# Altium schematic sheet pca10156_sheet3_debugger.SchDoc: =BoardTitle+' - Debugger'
size A3; Organization: Nordic Semiconductor; DocumentNumber: 3; SheetNumber: 3; SheetTotal: 8; CompanyName: Nordic Semiconductor; DocumentSize: A4
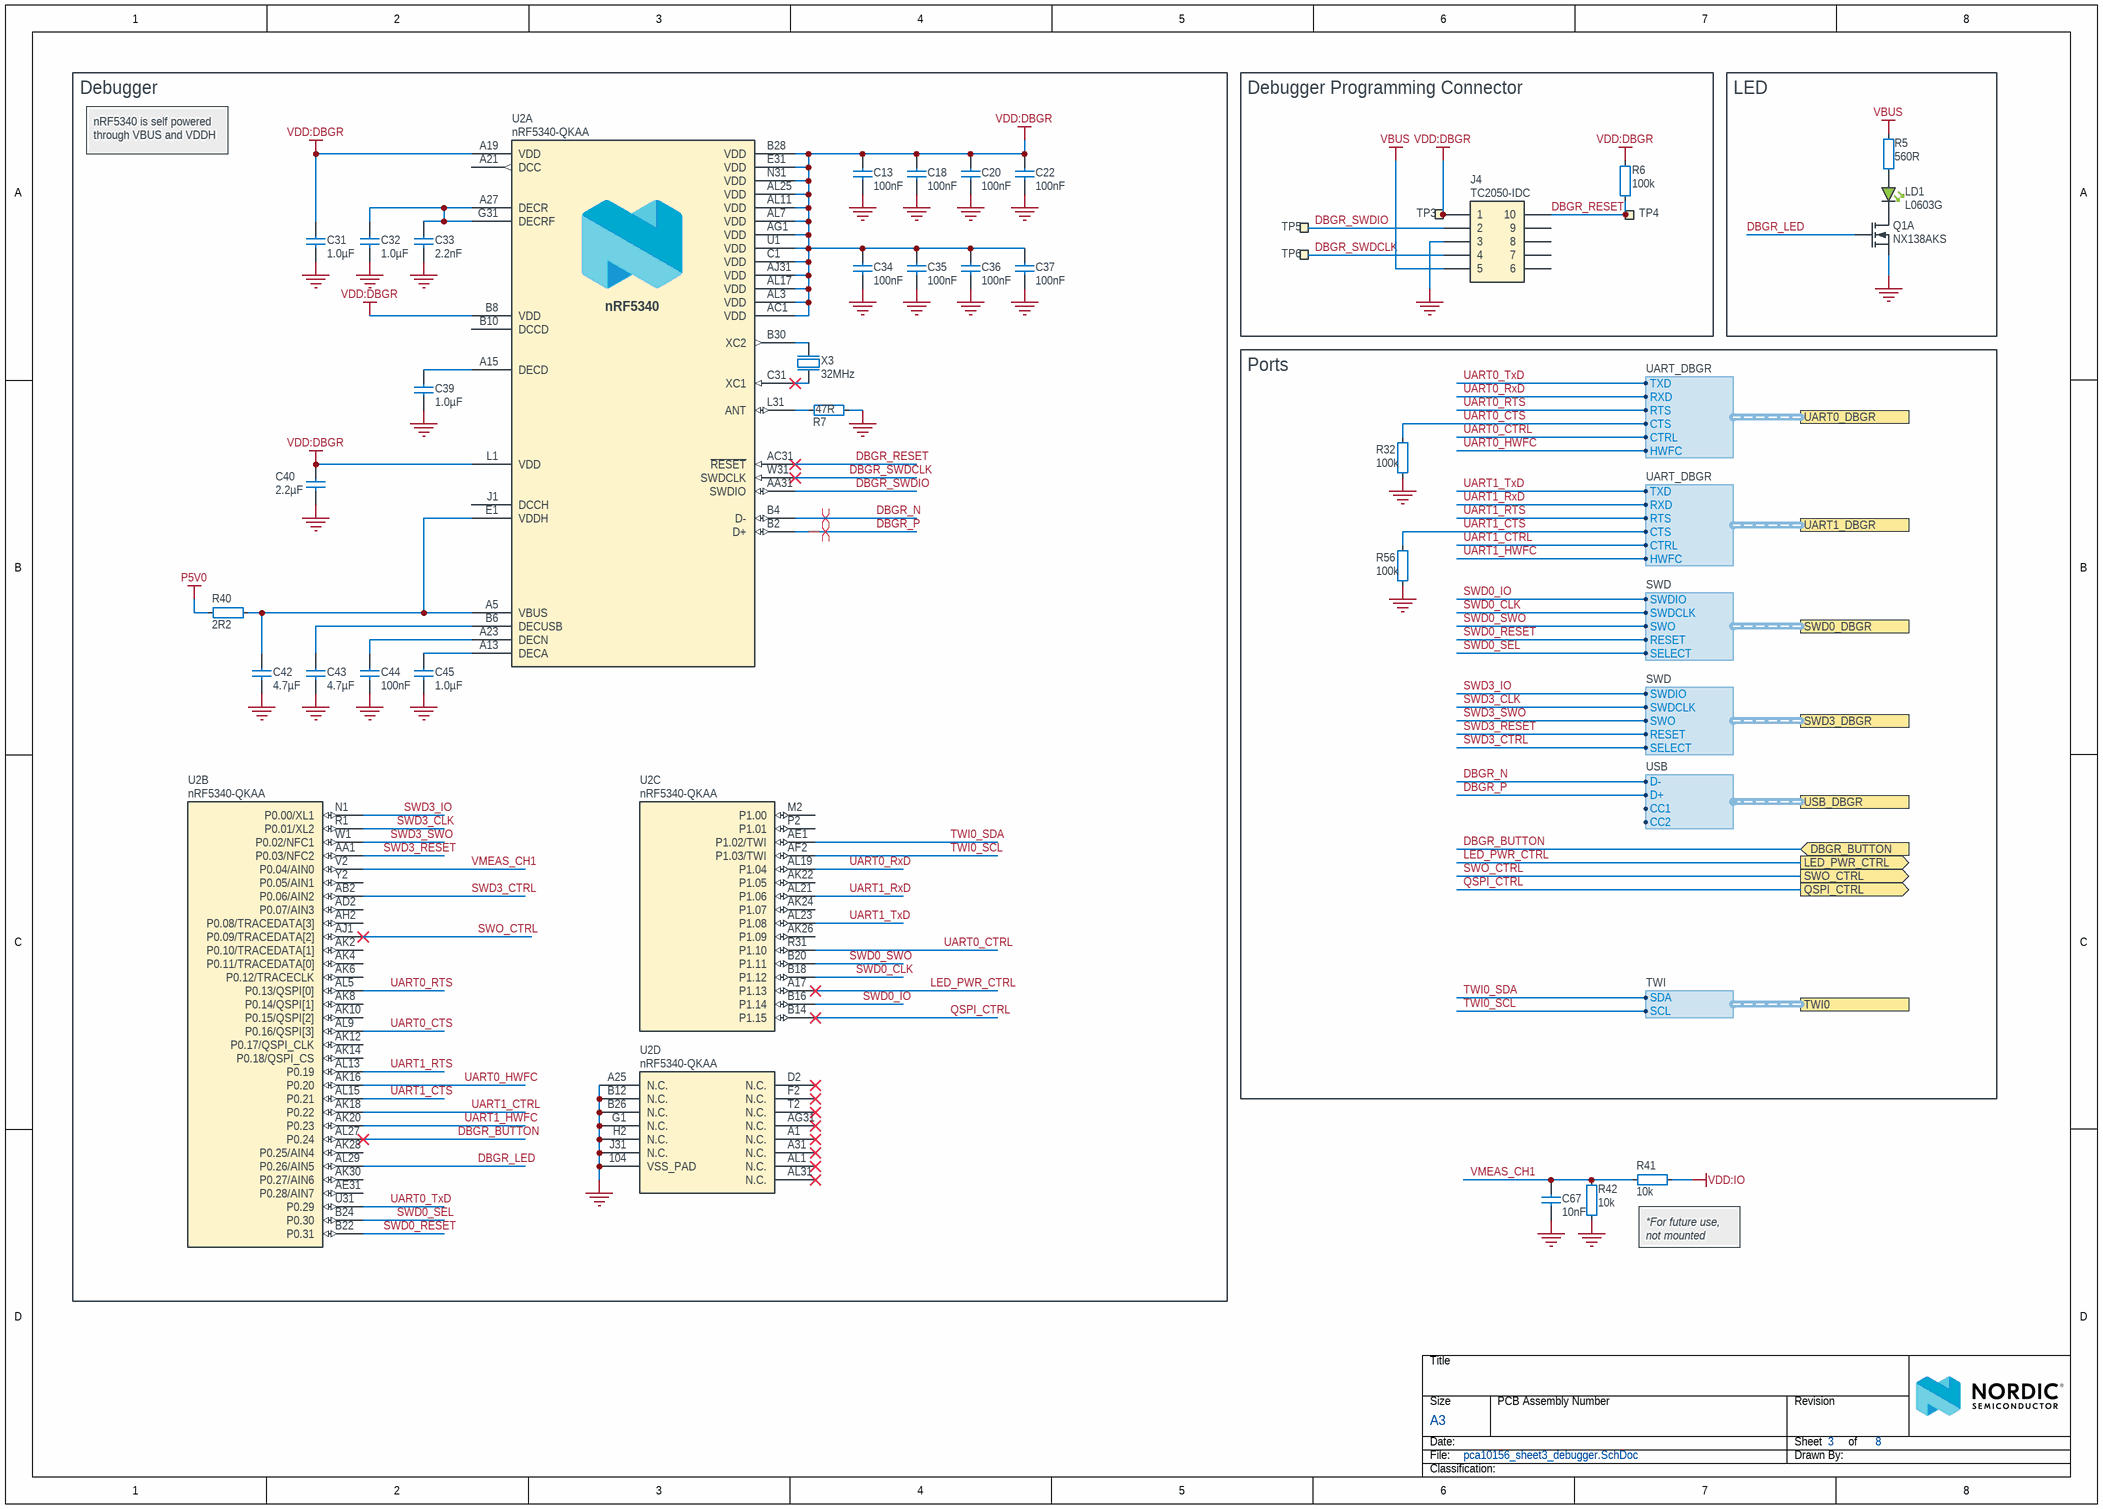
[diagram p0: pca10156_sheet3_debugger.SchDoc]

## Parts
C13  100nF  [CAPC0603X03L_C]
C18  100nF  [CAPC0603X03L_C]
C20  100nF  [CAPC0603X03L_C]
C22  100nF  [CAPC0603X03L_C]
C31  1.0µF  [CAPC1005X04L]
C32  1.0µF  [CAPC1005X04L]
C33  2.2nF  [CAPC0603X03L_C]
C34  100nF  [CAPC0603X03L_C]
C35  100nF  [CAPC0603X03L_C]
C36  100nF  [CAPC0603X03L_C]
C37  100nF  [CAPC0603X03L_C]
C39  1.0µF  [CAPC1005X04L]
C40  2.2µF  [CAPC1608X06L]
C42  4.7µF  [CAPC1608X06L]
C43  4.7µF  [CAPC1608X06L]
C44  100nF  [CAPC0603X03L_C]
C45  1.0µF  [CAPC1005X04L]
C67  10nF  [CAPC0603X03L_C]
J4  TC2050-IDC  [TC2050-IDC-NLFP]  (no BOM)
LD1  L0603G  [LED_0603_G]
Q1  NX138AKS  [TSSOP6]  (part A of 2)
R5  560R  [RESC0603X03L_C]
R6  100k  [RESC0603X03L_C]
R7  47R  [RESC0603X03L_C]
R32  100k  [RESC0603X03L_C]
R40  2R2  [RESC0603X03L_C]
R41  10k  [RESC0603X03L_C]
R42  10k  [RESC0603X03L_C]
R56  100k  [RESC0603X03L_C]
TP3  Ø1.5mm,SMD  [TP_SMD_D1.5mm]  (value not drawn)  (no BOM)
TP4  Ø1.5mm,SMD  [TP_SMD_D1.5mm]  (value not drawn)  (no BOM)
TP5  Ø1.5mm,SMD  [TP_SMD_D1.5mm]  (value not drawn)  (no BOM)
TP6  Ø1.5mm,SMD  [TP_SMD_D1.5mm]  (value not drawn)  (no BOM)
U2  nRF5340-QKAA  [AQFN40P700X700X85_HS-99N]  (parts A,B,C,D of 4)
X3  32MHz  [BT-XTAL_2016]

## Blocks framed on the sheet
Debugger: C13 C18 C20 C22 C31-C37 C39 C40 C42-C45 R7 R40 U2 X3
Debugger Programming Connector: J4 R6 TP3-TP6
LED: LD1 Q1 R5
Ports: R32 R56

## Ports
DBGR_BUTTON (in), LED_PWR_CTRL (out), QSPI_CTRL (out), SWD0_DBGR (harness SWD), SWD3_DBGR (harness SWD), SWO_CTRL (out), TWI0 (harness TWI), UART0_DBGR (harness UART_DBGR), UART1_DBGR (harness UART_DBGR), USB_DBGR (harness USB)

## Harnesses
SWD: SWDIO, SWDCLK, SWO, RESET, SELECT
UART_DBGR: RTS, CTS, RXD, TXD, HWFC, CTRL
TWI: SCL, SDA
USB: D+, D-, CC1, CC2

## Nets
GND: C13.2 C18.2 C20.2 C22.2 C31.2 C32.1 C33.2 C34.2 C35.2 C36.2 C37.2 C39.1 C40.2 C42.2 C43.2 C44.2 C45.1 C67.2 J4.3 Q1.1(S1) R7.2 R32.2 R42.1 R56.2 U2.104(VSS_PAD) U2.A25(N.C.) U2.B12(N.C.) U2.B26(N.C.) U2.G1(N.C.) U2.H2(N.C.) U2.J31(N.C.) X3.2(GND) X3.4(GND)
P5V0: R40.2
VBUS: J4.5 R5.2
VDD:DBGR: C13.1 C18.1 C20.1 C22.1 C31.1 C34.1 C35.1 C36.1 C37.1 C40.1 J4.1 R6.2 TP3.1 U2.A19(VDD) U2.AC1(VDD) U2.AG1(VDD) U2.AJ31(VDD) U2.AL3(VDD) U2.AL7(VDD) U2.AL11(VDD) U2.AL17(VDD) U2.AL25(VDD) U2.B8(VDD) U2.B28(VDD) U2.C1(VDD) U2.E31(VDD) U2.L1(VDD) U2.N31(VDD) U2.U1(VDD)
VDD:IO: R41.2
DBGR_BUTTON: U2.AL27(P0.24) ; port DBGR_BUTTON
DBGR_LED: Q1.2(G1) U2.AL29(P0.26/AIN5)
DBGR_N: U2.B4(D-) ; port USB_DBGR.D-
DBGR_P: U2.B2(D+) ; port USB_DBGR.D+
DBGR_RESET: J4.10 R6.1 TP4.1 U2.AC31(~{RESET})
DBGR_SWDCLK: J4.4 TP6.1 U2.W31(SWDCLK)
DBGR_SWDIO: J4.2 TP5.1 U2.AA31(SWDIO)
LED_PWR_CTRL: U2.A17(P1.13) ; port LED_PWR_CTRL
QSPI_CTRL: U2.B14(P1.15) ; port QSPI_CTRL
SWD0_CLK: U2.B18(P1.12) ; port SWD0_DBGR.SWDCLK
SWD0_IO: U2.B16(P1.14) ; port SWD0_DBGR.SWDIO
SWD0_RESET: U2.B22(P0.31) ; port SWD0_DBGR.RESET
SWD0_SEL: U2.B24(P0.30) ; port SWD0_DBGR.SELECT
SWD0_SWO: U2.B20(P1.11) ; port SWD0_DBGR.SWO
SWD3_CLK: U2.R1(P0.01/XL2) ; port SWD3_DBGR.SWDCLK
SWD3_CTRL: U2.AB2(P0.06/AIN2) ; port SWD3_DBGR.SELECT
SWD3_IO: U2.N1(P0.00/XL1) ; port SWD3_DBGR.SWDIO
SWD3_RESET: U2.AA1(P0.03/NFC2) ; port SWD3_DBGR.RESET
SWD3_SWO: U2.W1(P0.02/NFC1) ; port SWD3_DBGR.SWO
SWO_CTRL: U2.AJ1(P0.09/TRACEDATA[2]) ; port SWO_CTRL
TWI0_SCL: U2.AF2(P1.03/TWI) ; port TWI0.SCL
TWI0_SDA: U2.AE1(P1.02/TWI) ; port TWI0.SDA
UART0_CTRL: U2.R31(P1.10) ; port UART0_DBGR.CTRL
UART0_CTS: R32.1 U2.AL9(P0.16/QSPI[3]) ; port UART0_DBGR.CTS
UART0_HWFC: U2.AK16(P0.20) ; port UART0_DBGR.HWFC
UART0_RTS: U2.AL5(P0.13/QSPI[0]) ; port UART0_DBGR.RTS
UART0_RxD: U2.AL19(P1.04) ; port UART0_DBGR.RXD
UART0_TxD: U2.U31(P0.29) ; port UART0_DBGR.TXD
UART1_CTRL: U2.AK18(P0.22) ; port UART1_DBGR.CTRL
UART1_CTS: R56.1 U2.AL15(P0.21) ; port UART1_DBGR.CTS
UART1_HWFC: U2.AK20(P0.23) ; port UART1_DBGR.HWFC
UART1_RTS: U2.AL13(P0.19) ; port UART1_DBGR.RTS
UART1_RxD: U2.AL21(P1.06) ; port UART1_DBGR.RXD
UART1_TxD: U2.AL23(P1.08) ; port UART1_DBGR.TXD
VMEAS_CH1: C67.1 R41.1 R42.2 U2.V2(P0.04/AIN0)
NetC32_2: C32.2 C33.1 U2.A27(DECR) U2.G31(DECRF)
NetC39_2: C39.2 U2.A15(DECD)
NetC42_1: C42.1 R40.1 U2.A5(VBUS) U2.E1(VDDH)
NetC43_1: C43.1 U2.B6(DECUSB)
NetC44_1: C44.1 U2.A23(DECN)
NetC45_2: C45.2 U2.A13(DECA)
NetLD1_1: LD1.1(C) Q1.6(D1)
NetLD1_2: LD1.2(A) R5.1
NetR7_1: R7.1 U2.L31(ANT)
NetU2_B30: U2.B30(XC2) X3.3(out)
NetU2_C31: U2.C31(XC1) X3.1(inp)

Not connected (* = marked no-connect by the designer): J4 6 7 8 9; U2 A1(N.C.)* A21(DCC) A31(N.C.)* AD2(P0.07/AIN3) AE31(P0.28/AIN7) AG31(N.C.)* AH2(P0.08/TRACEDATA[3]) AK2(P0.10/TRACEDATA[1]) AK4(P0.11/TRACEDATA[0]) AK6(P0.12/TRACECLK) AK8(P0.14/QSPI[1]) AK10(P0.15/QSPI[2]) AK12(P0.17/QSPI_CLK) AK14(P0.18/QSPI_CS) AK22(P1.05) AK24(P1.07) AK26(P1.09) AK28(P0.25/AIN4) AK30(P0.27/AIN6) AL1(N.C.)* AL31(N.C.)* B10(DCCD) D2(N.C.)* F2(N.C.)* J1(DCCH) M2(P1.00) P2(P1.01) T2(N.C.)* Y2(P0.05/AIN1)

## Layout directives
differential pair; differential pair class DBGR; net class DBGR_USB: DBGR_N, DBGR_P

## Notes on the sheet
- nRF5340 is self powered through VBUS and VDDH
- (near R41) *For future use, not mounted

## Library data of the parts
C13 C18 C20 C22 C34-C37 C44 = C0201-100n: Capacitor, X5R, ±10%; Manufacturer: N.A.; Part number IPS: 00000001248, 00000002505; Part number Norautron: 262071862; Part number NEMS: 100200078; Pad Count: 2; Note: 16V; Component Status: Active
C31 C32 C39 C45 = C0402-1µ0-6.3V-X5R-10%: Capacitor, X5R, ±10%, 6.3V; Manufacturer: N.A.; Part number Norautron: 26207137; Part number NEMS: 100200498; Pad Count: 2; Component Status: Active
C33 = C0201-2n2: Capacitor, X7R, ±10%, 10V; Manufacturer: N.A.; Part number IPS: 00000001778; Part number Norautron: 26470002; Part number NEMS: 100200060; Pad Count: 2; Component Status: Active
C40 = C0603-2µ2-6.3V-X7R: Capacitor, X7R, ±10%, 6.3V; Manufacturer: N.A.; Part number NEMS: 100200272; Artikkelnr Noca: 20039322; Pad Count: 2; Component Status: Active
C42 C43 = C0603-4µ7-10V-X7S: Capacitor, X7S, ±10%, 10V; Manufacturer: N.A.; Part number IPS: 00000001779; Part number NEMS: 100200351; Pad Count: 2; Artikkelnr Noca: 20030013; Component Status: Active
C67 = C0201-10n: Capacitor, X7R, ±10%; Manufacturer: N.A.; Part number IPS: 00000003480; Part number Norautron: 26621779; Part number NEMS: 100200067; Note: 10V; Assembly: Not Mounted; Pad Count: 2; Component Status: Active
J4 = TC2050-IDC-NLFP: CBL PLUG-OF-NAILS 10-PIN; Manufacturer: Tag-Connect LLC; Part number NEMS: 100500463; Artikkelnr Noca: N.A.; Pad Count: 10; Component Status: Active; System: Connector
LD1 = VS 25C7M5: LED, Green, 0603, 573nm, Vf=2.0V, 24mcd, - 40 to +85°C; Manufacturer: Victory Electronics; Part number IPS: 00000001274, 00000009961; Part number Norautron: 26313411; Part number NEMS: 101400097; Pad Count: 2; Note: N.A.; Artikkelnr Noca: 13019193; Component Status: Active
Q1 = NX138AKS: MOSFET 2N-CH 60V 0.17A TSSOP6 (SOT363); Manufacturer: Nexperia; Manufacturer Part Number: NX138AKSX; Part number NEMS: 101300207; Component Status: Active; Pad Count: 6; Note: N.A.
R5 = R0201-560: Resistor, ±1%, 0.05W; Manufacturer: N.A.; Part number NEMS: 100100038; Note: Chip Res 1%; Pad Count: 2; Component Status: Active
R6 R32 R56 = R0201-100k: Resistor, ±1%, 0.05W; Manufacturer: N.A.; Part number IPS: 00000001419; Part number Norautron: 26108487; Part number NEMS: 100100080; Note: Chip Res 1%; Pad Count: 2; Component Status: Active
R7 = R0201-47R: Resistor, ±1%, 0.05W; Manufacturer: N.A.; Part number IPS: 00000004794; Part number Norautron: 26108300; Part number NEMS: 100100022; Component Status: Active; Pad Count: 2; Note: Chip Res 1%
R40 = R0201-2R2: Resistor, ±1%, 0.05W; Manufacturer: N.A.; Part number Norautron: 26470029; Part number NEMS: 100100006; Pad Count: 2; Note: Chip Res 1%; Component Status: Active
R41 R42 = R0201-10k: Resistor, ±1%, 0.05W; Manufacturer: N.A.; Part number IPS: 00000001255; Part number Norautron: 26107101; Part number NEMS: 100100065; Component Status: Active; Pad Count: 2; Note: Chip Res 1%
TP3-TP6 = TP_SMD_Ø1.5MM: 1.5mm circular SMD testpad; Manufacturer: Nordic Semiconductor; Manufacturer Part Number: N.A.; Part number NEMS: 100500477; Pad Count: 1; Component Status: Active
U2 = nRF5340-QKAAD0: Multi-protocol Bluetooth Low Energy, IEEE 802.15.4, ANT and 2.4GHz proprietary system-on-chip; Manufacturer: Nordic Semiconductor; Part number Norautron: NOD26470035; Part number NEMS: 102000216; Pad Count: 98; Note: N.A.; Component Status: Active
X3 = XTAL_SMD2016_32MHz_8pF_Golledge: XTAL SMD 2016, 32MHz, Cl=8pF, Tol: ±10ppm, Stab: ±15ppm; Manufacturer Part Number: MP06003; Part number IPS: 00000001431; Part number Norautron: N.A.; Part number NEMS: 101600041; Component Status: Active; Pad Count: 4; Note: XTAL SMD 32.000MHz; Artikkelnr Noca: 22010050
